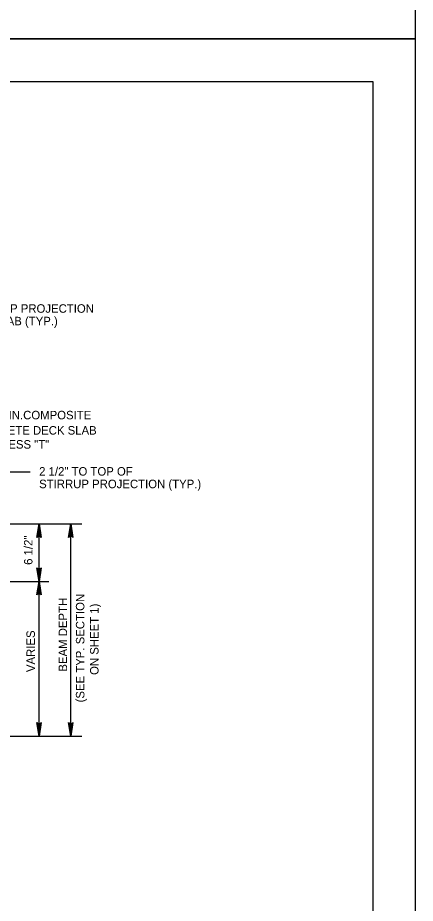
# Model space of a CAD drawing. Extents: x 642009 to 642864, y 298232 to 300014.
# Drawn here: x 642709.1 to 642849.7, y 298520.5 to 298833.3 of the extents above; entities that cross this region are included whole.
import ezdxf

# ---------------------------------------------------------------- set-up
doc = ezdxf.new("R2010")
doc.units = 0
for name, color, linetype in [('2', 7, 'Continuous'), ('22', 7, 'Continuous'), ('PLT-BNDY', 7, 'Continuous')]:
    doc.layers.add(name, color=color, linetype=linetype)

msp = doc.modelspace()

# ---------------------------------------------------------------- linework, layer by layer
at = {"layer": '2'}
for p, q in [((642048.66, 298810.82), (642834.66, 298810.82)), ((642834.66, 298810.82), (642834.66, 298246.82))]:
    msp.add_line(p, q, dxfattribs=at)
at = {"layer": '22'}
for p, q in [((642703.97, 298672.87), (642713.58, 298672.87)), ((642695.09, 298654.55), (642731.76, 298654.55)), ((642716.69, 298634.24), (642716.69, 298654.55)), ((642716.69, 298634.24), (642716.69, 298654.55)), ((642727.9, 298579.55), (642727.9, 298654.55)), ((642727.9, 298579.55), (642727.9, 298654.55)), ((642697.54, 298634.24), (642720.09, 298634.24)), ((642716.69, 298579.55), (642716.69, 298634.24)), ((642685.67, 298579.55), (642731.76, 298579.55))]:
    msp.add_line(p, q, dxfattribs=at)
for points in [[(642716.12, 298650.01), (642716.45, 298650.18), (642716.69, 298654.55), (642716.12, 298650.01), (642715.92, 298649.77), (642716.69, 298654.55), (642716.9, 298650.18), (642717.23, 298650.02), (642716.69, 298654.55), (642717.45, 298649.77), (642717.23, 298650.02)], [(642727.33, 298650.01), (642727.66, 298650.18), (642727.9, 298654.55), (642727.33, 298650.01), (642727.13, 298649.77), (642727.9, 298654.55), (642728.11, 298650.18), (642728.44, 298650.02), (642727.9, 298654.55), (642728.66, 298649.77), (642728.44, 298650.02)], [(642717.26, 298638.78), (642716.93, 298638.61), (642716.69, 298634.24), (642717.26, 298638.78), (642717.46, 298639.01), (642716.69, 298634.24), (642716.47, 298638.6), (642716.15, 298638.76), (642716.69, 298634.24), (642715.93, 298639.01), (642716.15, 298638.76)], [(642716.12, 298629.7), (642716.45, 298629.86), (642716.69, 298634.24), (642716.12, 298629.7), (642715.92, 298629.46), (642716.69, 298634.24), (642716.9, 298629.87), (642717.23, 298629.71), (642716.69, 298634.24), (642717.45, 298629.46), (642717.23, 298629.71)], [(642717.26, 298584.09), (642716.93, 298583.92), (642716.69, 298579.55), (642717.26, 298584.09), (642717.46, 298584.33), (642716.69, 298579.55), (642716.47, 298583.92), (642716.15, 298584.08), (642716.69, 298579.55), (642715.93, 298584.33), (642716.15, 298584.08)], [(642728.47, 298584.09), (642728.14, 298583.92), (642727.9, 298579.55), (642728.47, 298584.09), (642728.67, 298584.33), (642727.9, 298579.55), (642727.68, 298583.92), (642727.36, 298584.08), (642727.9, 298579.55), (642727.14, 298584.33), (642727.36, 298584.08)]]:
    msp.add_lwpolyline(points, dxfattribs=at)
at = {"layer": 'PLT-BNDY'}
for points in [[(642008.66, 299419.82), (642849.66, 299419.82), (642849.66, 298825.82), (642008.66, 298825.82)], [(642008.66, 298825.82), (642849.66, 298825.82), (642849.66, 298231.82), (642008.66, 298231.82)]]:
    msp.add_lwpolyline(points, close=True, dxfattribs=at)

# ---------------------------------------------------------------- texts
at = {"layer": '22'}
for s, height, rotation, p in [('2" MIN. STIRRUP PROJECTION', 2.9997, 360, (642677.15, 298729.11)), ('INTO BEAM SLAB (TYP.)', 2.9997, 360, (642677.15, 298724.67)), ('5 1/2" MIN.COMPOSITE ', 2.9997, 360, (642691.13, 298691.46)), ('CONCRETE DECK SLAB', 2.9997, 360, (642690.9, 298686.07)), ('THICKNESS "T"', 2.9997, 360, (642690.9, 298681.12)), ('2 1/2" TO TOP OF', 2.9997, 360, (642716.71, 298671.58)), ('STIRRUP PROJECTION (TYP.)', 2.9997, 360, (642716.71, 298667.14)), ('6 1/2"', 3, 90, (642714.35, 298640.06)), ('(SEE TYP. SECTION', 2.9997, 90, (642732.7, 298591.48)), ('BEAM DEPTH', 3, 90, (642726.59, 298602.34)), ('ON SHEET 1)', 2.9997, 90, (642737.7, 298601.18)), ('VARIES', 3, 90, (642715.22, 298602.19))]:
    msp.add_text(s, height=height, rotation=rotation, dxfattribs=at).set_placement(p)

doc.saveas('drawing.dxf')
